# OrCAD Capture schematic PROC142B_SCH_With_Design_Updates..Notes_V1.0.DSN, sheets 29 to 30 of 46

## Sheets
29 28. BOOT MODE BUFFER & SWITCHES: size C; title: BOOT MODE CONFIGURATION BUFFERS & DIP SWITCHES
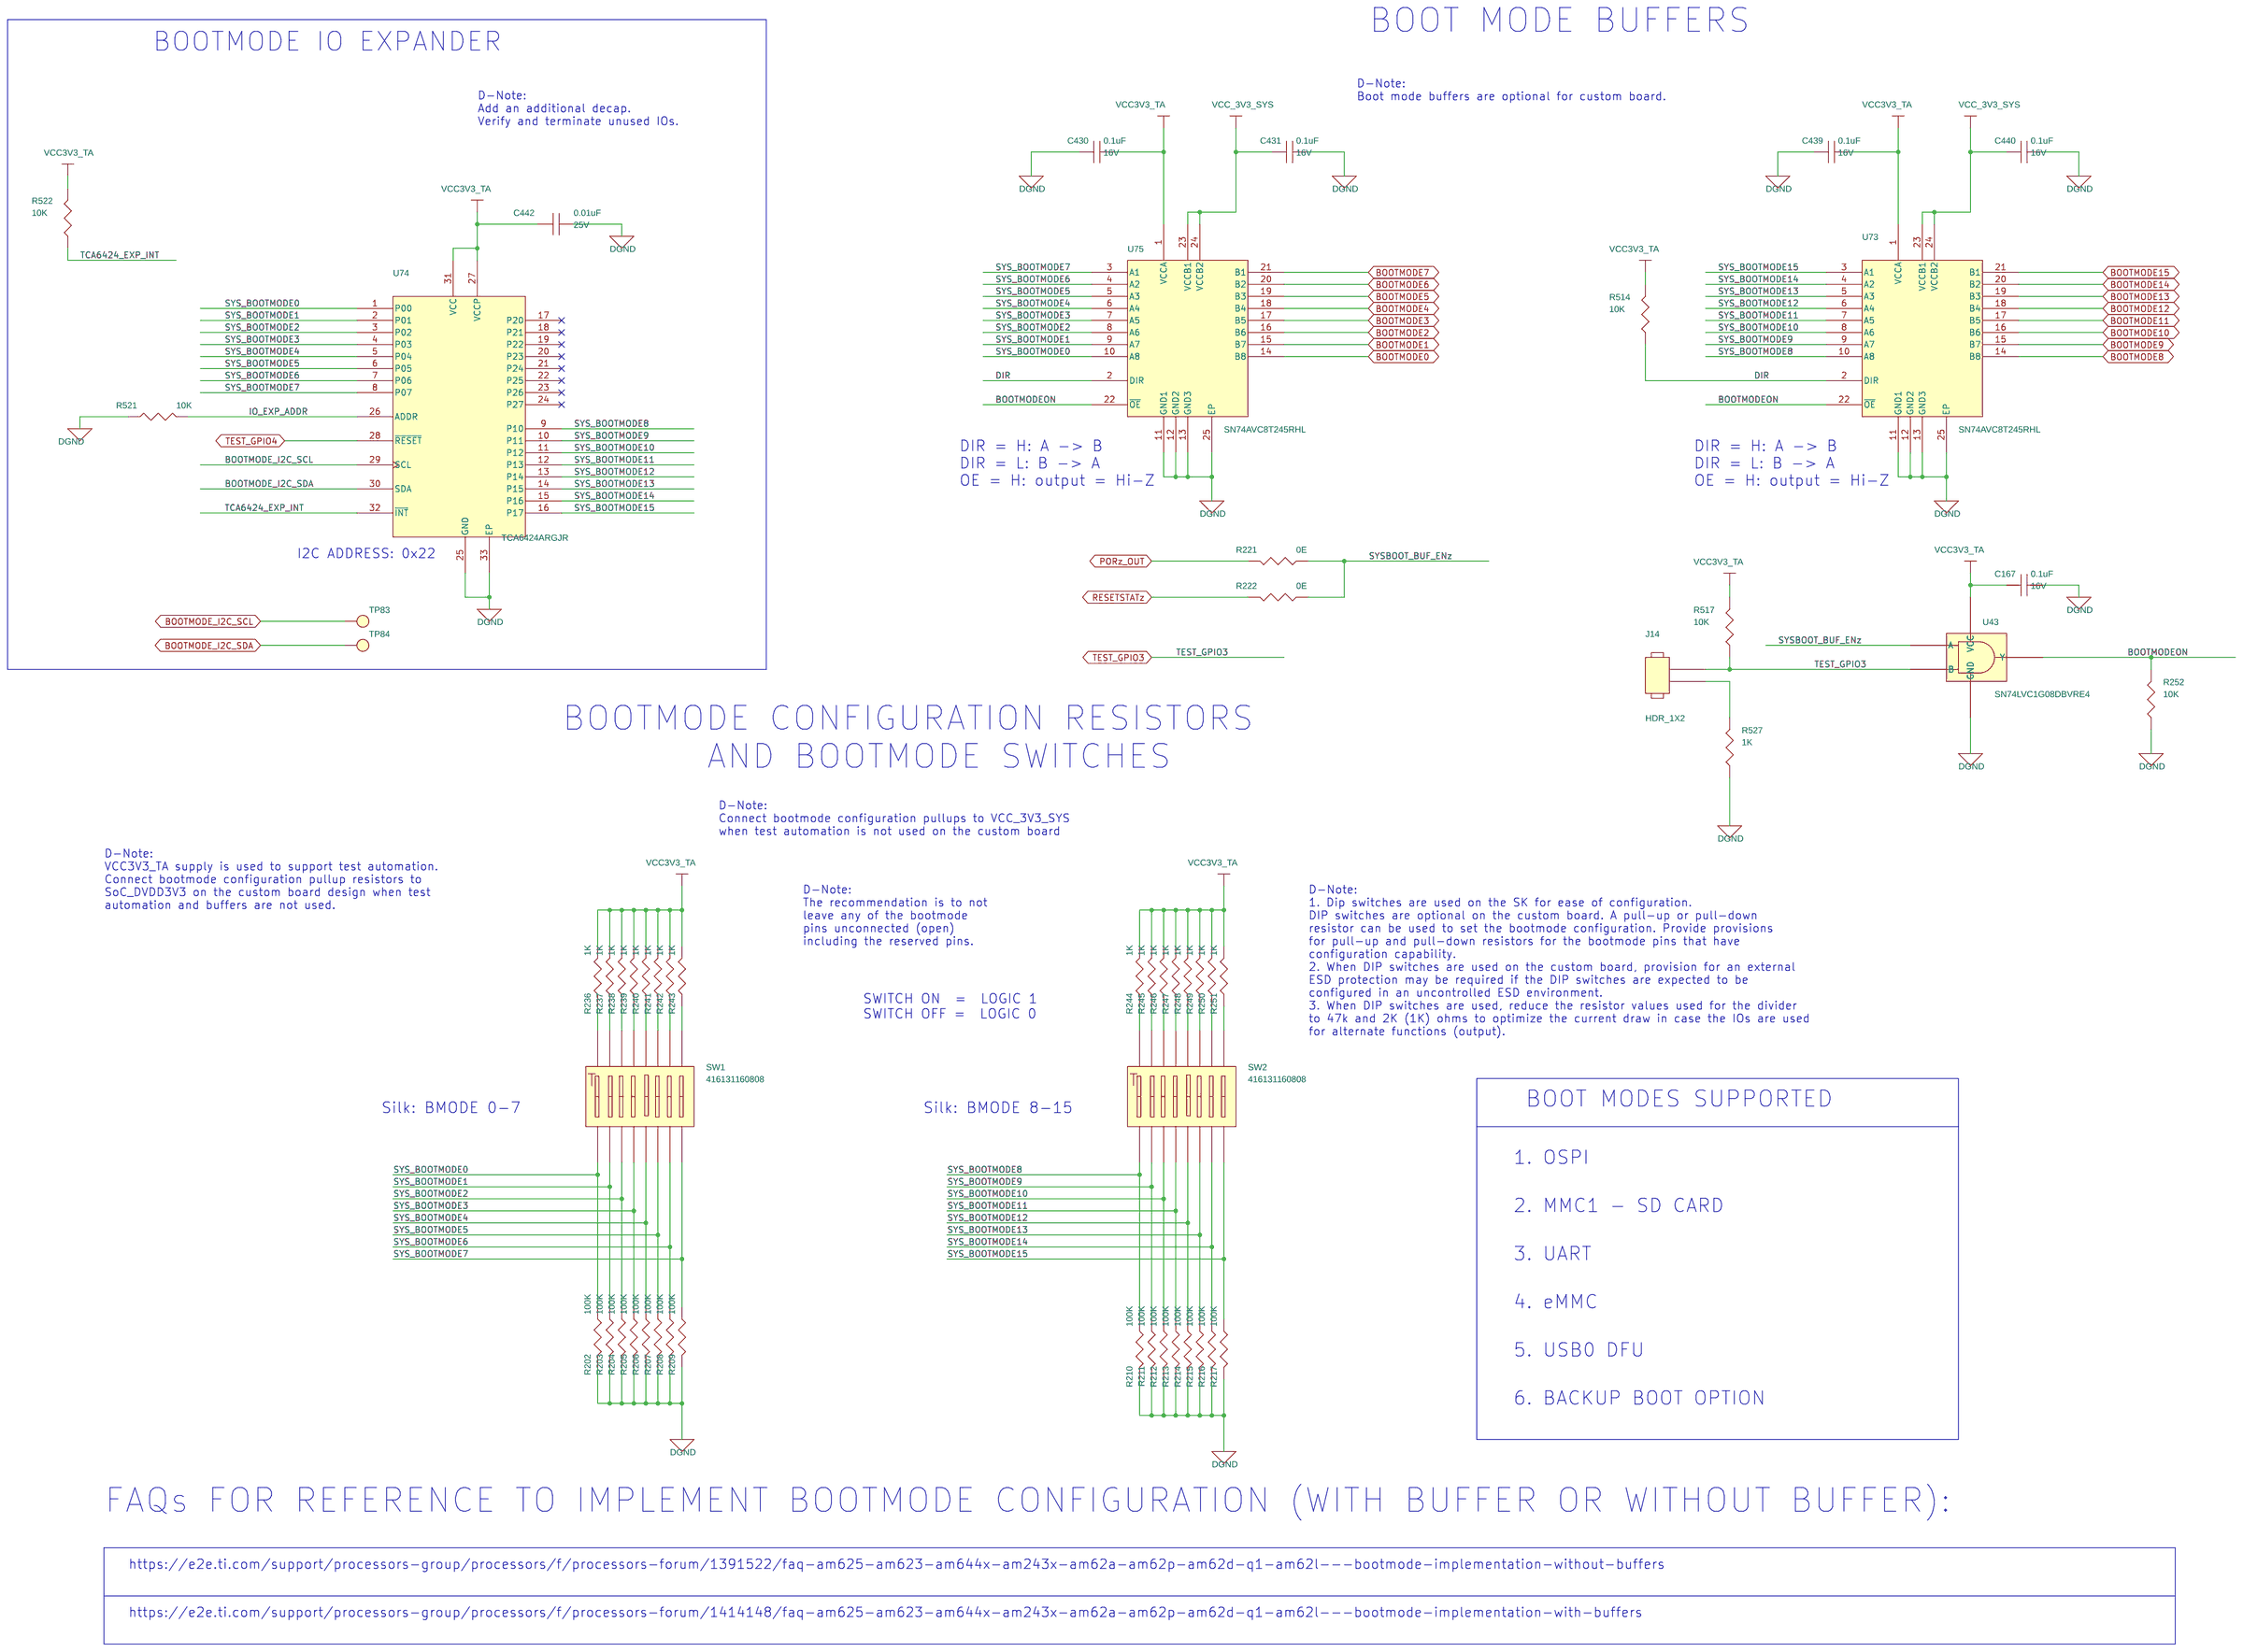
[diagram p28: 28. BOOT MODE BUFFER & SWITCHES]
30 29. XDS110 DEBUGGER: size C; title: XDS110 DEBUGGER
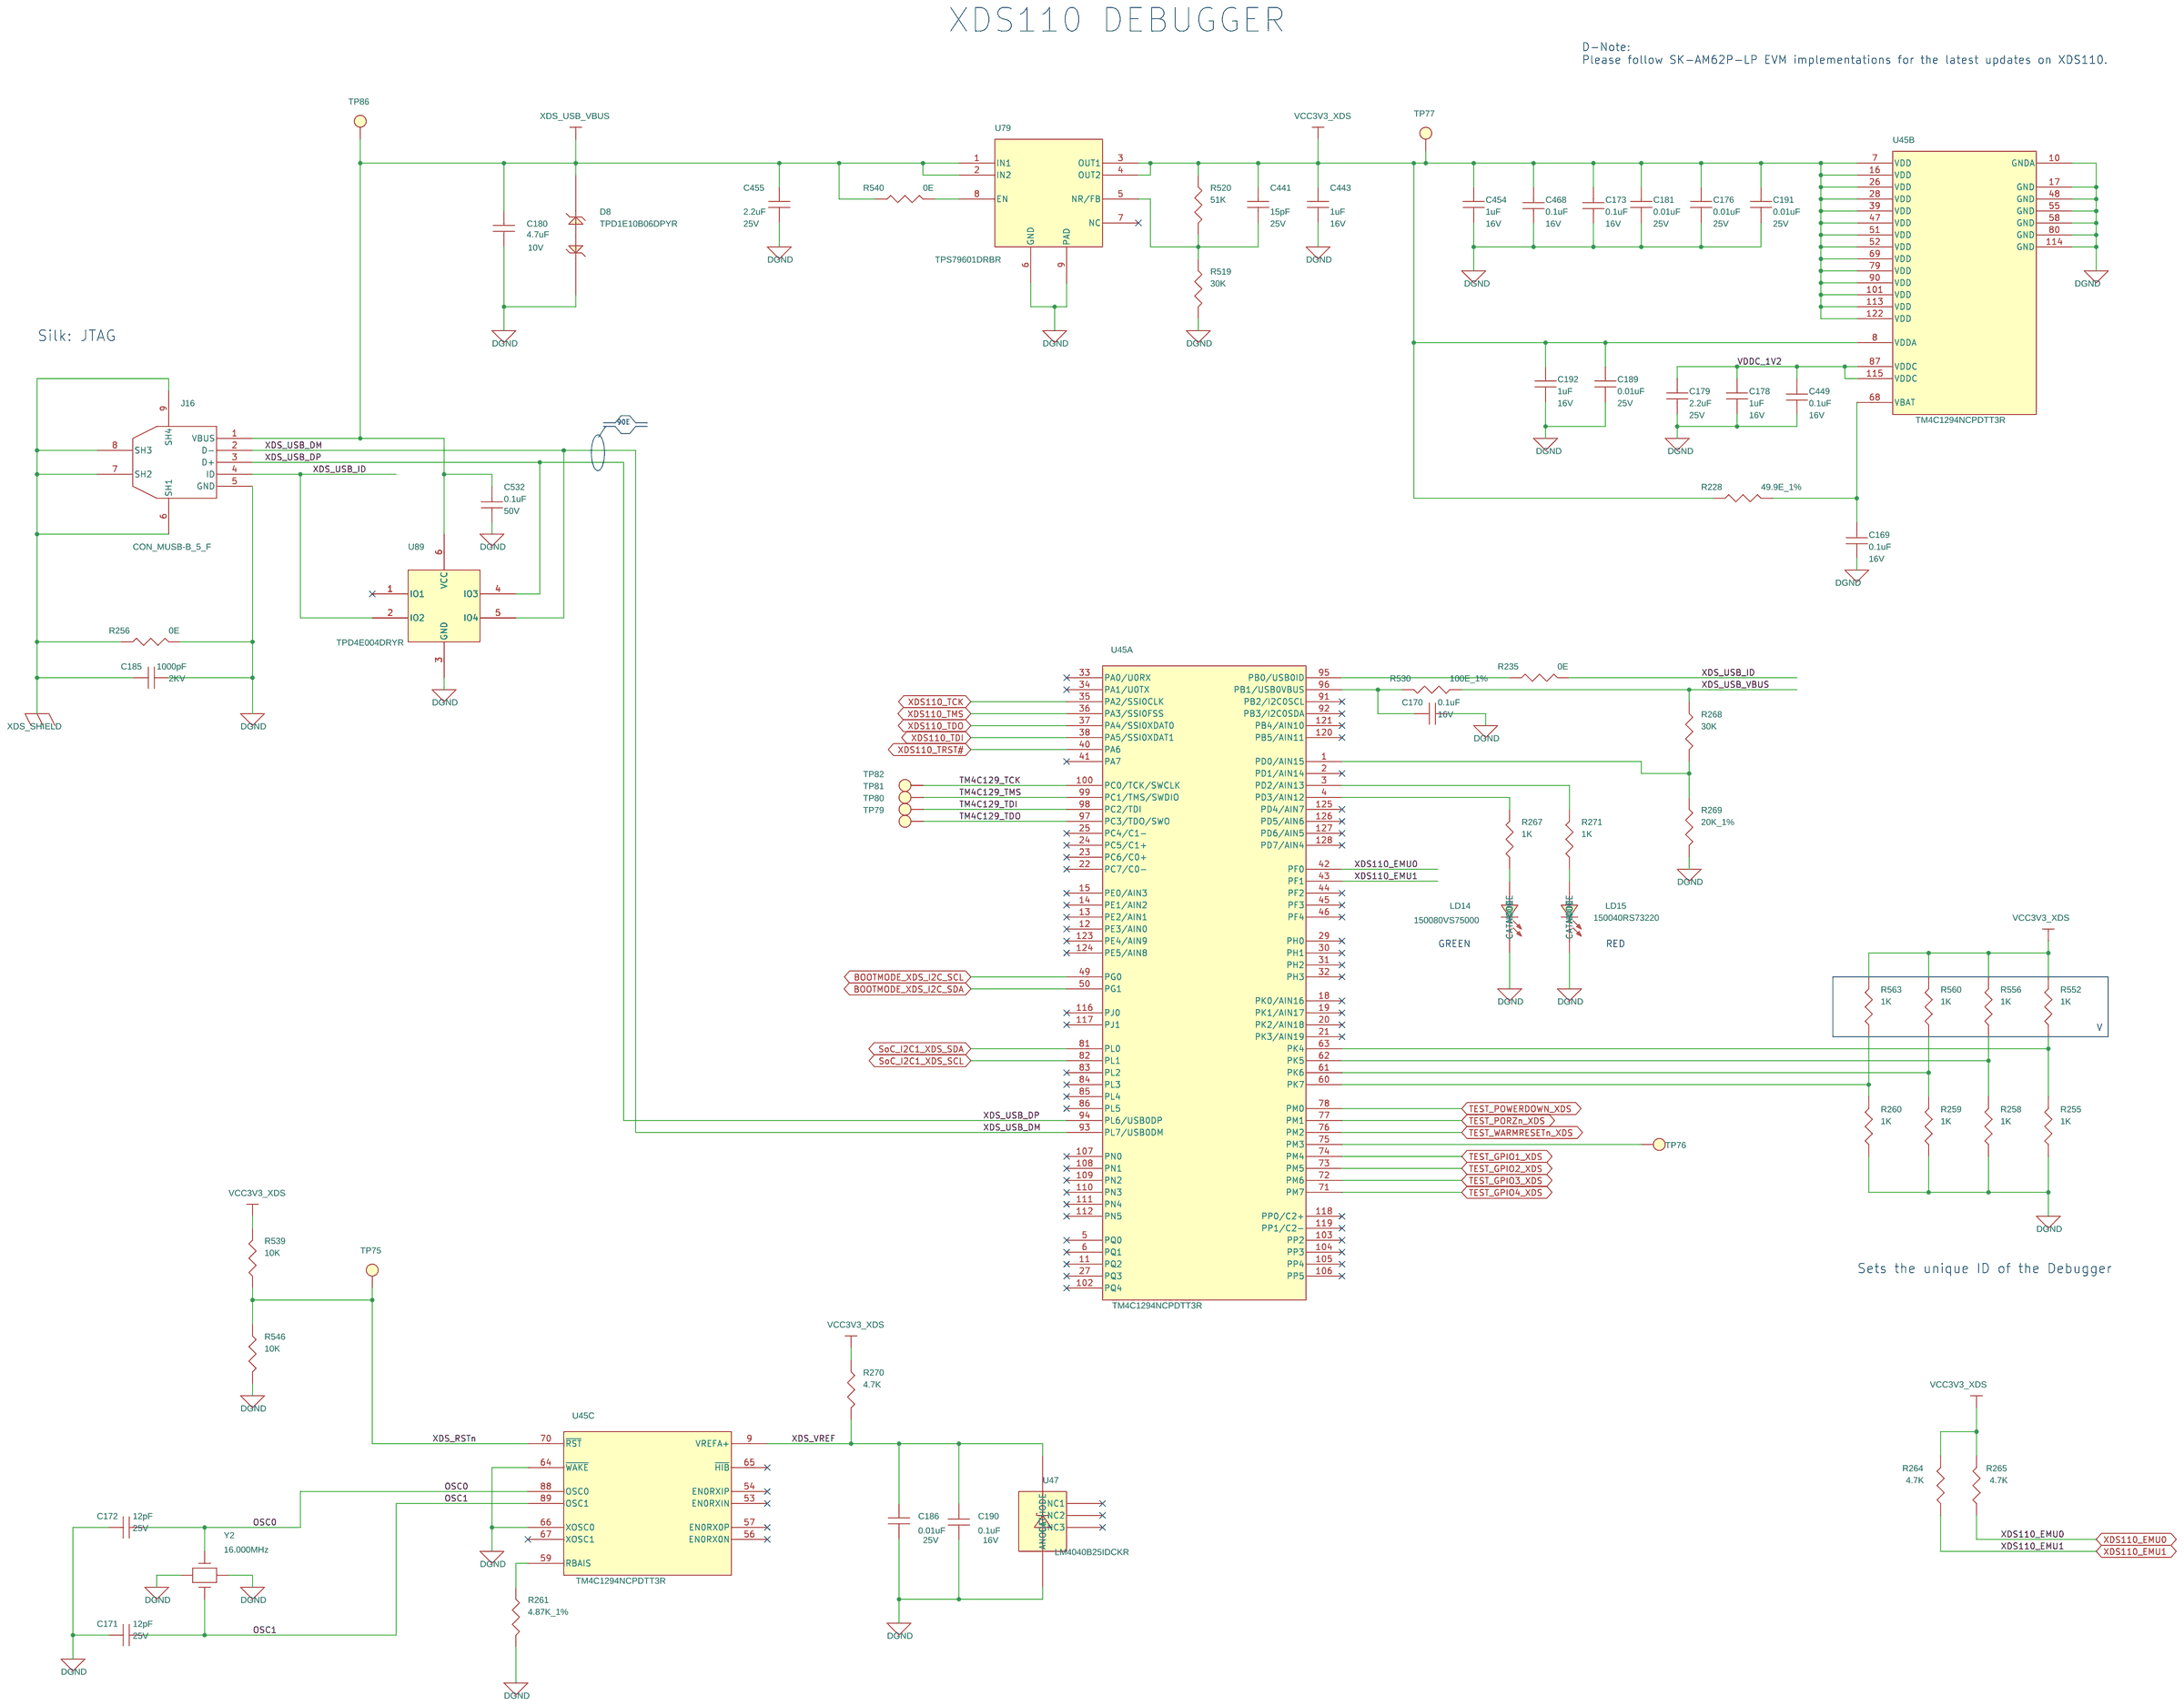
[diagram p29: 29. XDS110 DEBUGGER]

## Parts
sheet 28. BOOT MODE BUFFER & SWITCHES
C167  0.1uF  [CAP0201_0-5]
C430  0.1uF  [CAP0201_0-5]
C431  0.1uF  [CAP0201_0-5]
C439  0.1uF  [CAP0201_0-5]
C440  0.1uF  [CAP0201_0-5]
C442  0.01uF  [CAP0201_0-5]
J14  HDR_1X2  [HDR_1X2_90120-0122_S_T_5-6]
R202  100K  [RES0402_0-5]
R203  100K  [RES0402_0-5]
R204  100K  [RES0402_0-5]
R205  100K  [RES0402_0-5]
R206  100K  [RES0402_0-5]
R207  100K  [RES0402_0-5]
R208  100K  [RES0402_0-5]
R209  100K  [RES0402_0-5]
R210  100K  [RES0402_0-5]
R211  100K  [RES0402_0-5]
R212  100K  [RES0402_0-5]
R213  100K  [RES0402_0-5]
R214  100K  [RES0402_0-5]
R215  100K  [RES0402_0-5]
R216  100K  [RES0402_0-5]
R217  100K  [RES0402_0-5]
R221  0E  [RES0201_0-5]
R222  0E  [RES0402_0-5]
R236  1K  [RES0402_0-5]
R237  1K  [RES0402_0-5]
R238  1K  [RES0402_0-5]
R239  1K  [RES0402_0-5]
R240  1K  [RES0402_0-5]
R241  1K  [RES0402_0-5]
R242  1K  [RES0402_0-5]
R243  1K  [RES0402_0-5]
R244  1K  [RES0402_0-5]
R245  1K  [RES0402_0-5]
R246  1K  [RES0402_0-5]
R247  1K  [RES0402_0-5]
R248  1K  [RES0402_0-5]
R249  1K  [RES0402_0-5]
R250  1K  [RES0402_0-5]
R251  1K  [RES0402_0-5]
R252  10K  [RES0201_0-5]
R514  10K  [RES0201_0-5]
R517  10K  [RES0201_0-5]
R521  10K  [RES0201_0-5]
R522  10K  [RES0201_0-5]
R527  1K  [RES0402_0-5]
SW1  416131160808  [SW16_416131160808_460X230_SMD_2-7]
SW2  416131160808  [SW16_416131160808_460X230_SMD_2-7]
TP83  TP20_SMD  [TP20_SMD]
TP84  TP20_SMD  [TP20_SMD]
U43  SN74LVC1G08DBVRE4  [SOT23-5]
U73  SN74AVC8T245RHL  [QFN24_19-68_220X140_1]
U74  TCA6424ARGJR  [QFN32_19-68_200X200]
U75  SN74AVC8T245RHL  [QFN24_19-68_220X140_1]
sheet 29. XDS110 DEBUGGER
C169  0.1uF  [CAP0201_0-5]
C170  0.1uF  [CAP0201_0-5]
C171  12pF  [CAP0201_0-5]
C172  12pF  [CAP0201_0-5]
C173  0.1uF  [CAP0201_0-5]
C176  0.01uF  [CAP0201_0-5]
C178  1uF  [CAP0201_0-5]
C179  2.2uF  [CAP0402_0-75]
C180  4.7uF  [CAP0402_0-75]
C181  0.01uF  [CAP0201_0-5]
C185  1000pF  [CAP1206_1-75]
C186  0.01uF  [CAP0201_0-5]
C189  0.01uF  [CAP0201_0-5]
C190  0.1uF  [CAP0201_0-5]
C191  0.01uF  [CAP0201_0-5]
C192  1uF  [CAP0201_0-5]
C441  15pF  [CAP0201_0-5]
C443  1uF  [CAP0201_0-5]
C449  0.1uF  [CAP0201_0-5]
C454  1uF  [CAP0201_0-5]
C455  2.2uF  [CAP0402_0-75]
C468  0.1uF  [CAP0201_0-5]
C532  0.1uF  [CAP0402_0-75]
D8  TPD1E10B06DPYR  [DIO_DFN0402_0-5]
J16  CON_MUSB-B_5_F  [CON_MUSBB5_629105150521_S_R_S_2-7]
LD14  150080VS75000  [LED_150080VS75000_80X50_SMD_0-8]
LD15  150040RS73220  [LED_150040GS73220_40X20_SMD_0-4]
R228  49.9E_1%  [RES0402_0-5]
R235  0E  [RES0402_0-5]
R255  1K  [RES0402_0-5]
R256  0E  [RES0603_0-75]
R258  1K  [RES0402_0-5]
R259  1K  [RES0402_0-5]
R260  1K  [RES0402_0-5]
R261  4.87K_1%  [RES0402]
R264  4.7K  [RES0201_0-5]
R265  4.7K  [RES0201_0-5]
R267  1K  [RES0402_0-5]
R268  30K  [RES0402_0-5]
R269  20K_1%  [RES0402_0-5]
R270  4.7K  [RES0201_0-5]
R271  1K  [RES0402_0-5]
R519  30K  [RES0402_0-5]
R520  51K  [RES0402_0-5]
R530  100E_1%  [RES0402_0-5]
R539  10K  [RES0201_0-5]
R540  0E  [RES0201_0-5]
R546  10K  [RES0201_0-5]
R552  1K  [RES0402_0-5]
R556  1K  [RES0402_0-5]
R560  1K  [RES0402_0-5]
R563  1K  [RES0402_0-5]
TP75  TP20_SMD  [TP20_SMD]
TP76  TP20_SMD  [TP20_SMD]
TP77  TP20_SMD  [TP20_SMD]
TP79  TP20_SMD  [TP20_SMD]
TP80  TP20_SMD  [TP20_SMD]
TP81  TP20_SMD  [TP20_SMD]
TP82  TP20_SMD  [TP20_SMD]
TP86  TP20_SMD  [TP20_SMD]
U45  TM4C1294NCPDTT3R  [TQFP128_15-74_550X550_1-2]  (sections A,B,C)
U47  LM4040B25IDCKR  [SC70-5_1-1]
U79  TPS79601DRBR  [SON8_25-59_130X130_1]
U89  TPD4E004DRYR  [SON6_19-68_40X60_PB_0-6]
Y2  16.000MHz  [XTAL4_XRCGB-FM_80X60_SMD_0-7]

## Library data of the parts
C167 C169 C170 C173 C190 C430 C431 C439 C440 C449 C468 = CAP: CAP CERAMIC 0.1uF 16V 10% X5R 0201; Alt_Mfr_name: YAGEO AMERICA; Alt_Mfr_part_number: CC0402KRX5R8BB104; Chkd/date: MANIRAJA/230118; Crtd /date: MANIRAJA/230118; Custom_Duty: 15%; Customs_HS_Code: 85322990; Distributor_name: DIGIKEY; Distributor_part_number: 490-14305-1-ND; Footprint Path: Y:\MIS_DATABASE\Library\ALTIUM_TOOL\PCB_FOOTPRINTS\Altium_Footprint_Lib.PcbLib; Height: 0.33MM; Library Path: Y:\MIS_DATABASE\Library\ALTIUM_TOOL\SCHEMATICS_PARTS\MS_DISCRETE_Library.schlib; Mfr_name: MURATA; Mfr_part_number: GRM033R61C104KE14D; Mistral Part No: 120009030072-R; Package: 0201; Part_type: CAPACITORS\CERAMIC; Project: TI_MAXIE_CPB; RoHS: RoHS; Temperature: -55°C+85°C; Tolerance: 10%; Voltage: 16V; Wattage: NA; Weight: 0.33mg; Datasheet: Y:\MIS_DATABASE\DATASHEETS\CAPACITORS\GRM033R61C104KE14.PDF
C176 C181 C186 C189 C191 C442 = CAP: CAP CERAMIC 0.01uF 25V 10% X5R 0201; Chkd/date: MANIRAJA/230118; Crtd /date: MANIRAJA/230118; Custom_Duty: 15%; Customs_HS_Code: 85322990; Distributor_name: DIGIKEY; Distributor_part_number: GRM033R61E103KA12J-ND; Footprint Path: Y:\MIS_DATABASE\Library\ALTIUM_TOOL\PCB_FOOTPRINTS\Altium_Footprint_Lib.PcbLib; Height: 0.33MM; Library Path: Y:\MIS_DATABASE\Library\ALTIUM_TOOL\SCHEMATICS_PARTS\MS_DISCRETE_Library.schlib; Mfr_name: MURATA; Mfr_part_number: GRM033R61E103KA12J; Mistral Part No: 120018010007-R; Package: 0201; Part_type: CAPACITORS\CERAMIC; Project: TI_MAXIE_CPB; RoHS: RoHS; Temperature: -55°C+85°C; Tolerance: 10%; Voltage: 25V; Wattage: NA; Weight: 0.33mg; Datasheet: Y:\MIS_DATABASE\DATASHEETS\CAPACITORS\GRM033R61E103KA12.PDF
J14 = HEADER_2X1: CON HDR 1X2 2.54MM PITCH ST TH; Chkd/date: NAVEED/210714; Crtd /date: USMAN/031012; Custom_Duty: 24%; Customs_HS_Code: 85369090; Distributor_name: DIGIKEY; Distributor_part_number: WM8072-ND; Footprint Path: Y:\MIS_DATABASE\Library\ALTIUM_TOOL\PCB_FOOTPRINTS\Altium_Footprint_Lib.PcbLib; Height: 5.60MM; Library Path: Y:\MIS_DATABASE\Library\ALTIUM_TOOL\SCHEMATICS_PARTS\MS_CONNECTOR_Library.schlib; Mfr_name: MOLEX; Mfr_part_number: 90120-0122; Mistral Part No: 150012100005-R; Package: THRU-HOLE; Part_type: CONNECTOR\HEADERS; Project: NPOL_FEP; RoHS: RoHS; Temperature: -55°C+125°C; Tolerance: NA; Voltage: NA; Wattage: NA; Weight: 122mg; Datasheet: Y:\MIS_DATABASE\DATASHEETS\CONNECTORS\90120-XX.PDF
R202-R217 = RESISTOR: RES 100K 1/16W 5% 0402; Chkd/date: MANIRAJA/100717; Crtd /date: MANIRAJA/100717; Custom_Duty: 15%; Customs_HS_Code: 85332119; Distributor_name: DIGIKEY; Distributor_part_number: 311-100KJRCT-ND; Footprint Path: Y:\MIS_DATABASE\Library\ALTIUM_TOOL\PCB_FOOTPRINTS\Altium_Footprint_Lib.PcbLib; Height: 0.40MM; Library Path: Y:\MIS_DATABASE\Library\ALTIUM_TOOL\SCHEMATICS_PARTS\MS_DISCRETE_Library.schlib; Mfr_name: YAGEO AMERICA; Mfr_part_number: RC0402JR-07100KL; Mistral Part No: 110011060002-R; Package: 0402; Part_type: RESISTORS\FIXED; Project: DM8147_PCI CARD; RoHS: RoHS; Temperature: -55°C+155°C; Tolerance: 5%; Voltage: NA; Wattage: 1/16W; Weight: 0.65mg; Datasheet: Y:\MIS_DATABASE\DATASHEETS\RESISTORS\RCXXXXL-SER_MAR18.PDF
R221 R540 = RESISTOR: RES 0E 1/20W 5% 0201; Chkd/date: NAVEED/301214; Crtd /date: MUDDU/120710; Custom_Duty: 15%; Customs_HS_Code: 85332119; Distributor_name: DIGIKEY; Distributor_part_number: 311-0.0NCT-ND; Footprint Path: Y:\MIS_DATABASE\Library\ALTIUM_TOOL\PCB_FOOTPRINTS\Altium_Footprint_Lib.PcbLib; Height: 0.26MM; Library Path: Y:\MIS_DATABASE\Library\ALTIUM_TOOL\SCHEMATICS_PARTS\MS_DISCRETE_Library.schlib; Mfr_name: YAGEO AMERICA; Mfr_part_number: RC0201JR-070RL; Mistral Part No: 110010070067-R; Package: 0201; Part_type: RESISTORS\FIXED; Project: PB_BUGBASE; RoHS: RoHS; Temperature: -55°C+125°C; Tolerance: 5%; Voltage: NA; Wattage: 1/20W; Weight: 0.17mg; Datasheet: Y:\MIS_DATABASE\DATASHEETS\RESISTORS\RCXXXXL-SER_MAR18.PDF
R222 R235 = RESISTOR: RES 0E 1/16W JUMPER 0402; Chkd/date: VASANTHA/201216; Crtd /date: MUDDU/190810; Custom_Duty: 15%; Customs_HS_Code: 85332119; Distributor_name: DIGIKEY; Distributor_part_number: 541-0.0JCT-ND; Footprint Path: Y:\MIS_DATABASE\Library\ALTIUM_TOOL\PCB_FOOTPRINTS\Altium_Footprint_Lib.PcbLib; Height: 0.40MM; Library Path: Y:\MIS_DATABASE\Library\ALTIUM_TOOL\SCHEMATICS_PARTS\MS_DISCRETE_Library.schlib; Mfr_name: VISHAY; Mfr_part_number: CRCW04020000Z0ED; Mistral Part No: 110010080019-R; Package: 0402; Part_type: RESISTORS\FIXED; Project: PB_BUGBASE; RoHS: RoHS; Temperature: -55°C+155°C; Tolerance: NA; Voltage: NA; Wattage: 1/16W; Weight: 0.65mg; Datasheet: Y:\MIS_DATABASE\DATASHEETS\RESISTORS\CRCW0603.PDF
R236-R251 R255 R258-R260 R267 R271 R527 R552 R556 R560 R563 = RESISTOR: RES 1K 1/10W 5% 0402; Chkd/date: VASANTHA/201216; Crtd /date: MAZHAR/230805; Custom_Duty: 15%; Customs_HS_Code: 85332119; Distributor_name: DIGIKEY; Distributor_part_number: P1.0KJCT-ND; Footprint Path: Y:\MIS_DATABASE\Library\ALTIUM_TOOL\PCB_FOOTPRINTS\Altium_Footprint_Lib.PcbLib; Height: 0.40MM; Library Path: Y:\MIS_DATABASE\Library\ALTIUM_TOOL\SCHEMATICS_PARTS\MS_DISCRETE_Library.schlib; Mfr_name: PANASONIC-ECG; Mfr_part_number: ERJ-2GEJ102X; Mistral Part No: 110009030400-R; Package: 0402; Part_type: RESISTORS\FIXED; Project: HSE; RoHS: RoHS; Temperature: -55°C+155°C; Tolerance: 5%; Voltage: NA; Wattage: 1/10W; Weight: 0.8mg; Datasheet: Y:\MIS_DATABASE\DATASHEETS\RESISTORS\PAN-ERJSER_NOV17.PDF
R252 R514 R517 R521 R522 R539 R546 = RESISTOR: RES 10K 1/20W 5% 0201; Chkd/date: MANIRAJA/050517; Crtd /date: MANIRAJA/050517; Custom_Duty: 15%; Customs_HS_Code: 85332119; Distributor_name: DIGIKEY; Distributor_part_number: 311-10KNCT-ND; Footprint Path: Y:\MIS_DATABASE\Library\ALTIUM_TOOL\PCB_FOOTPRINTS\Altium_Footprint_Lib.PcbLib; Height: 0.26MM; Library Path: Y:\MIS_DATABASE\Library\ALTIUM_TOOL\SCHEMATICS_PARTS\MS_DISCRETE_Library.schlib; Mfr_name: YAGEO AMERICA; Mfr_part_number: RC0201JR-0710KL; Mistral Part No: 110010070051-R; Package: 0201; Part_type: RESISTORS\FIXED; Project: GOLDEN-I LITE; RoHS: RoHS; Temperature: -55°C+125°C; Tolerance: 5%; Voltage: NA; Wattage: 1/20W; Weight: 0.17mg; Datasheet: Y:\MIS_DATABASE\DATASHEETS\RESISTORS\RCXXXXL-SER_MAR18.PDF
SW1 SW2 = SW16_CHS-08A: SWITCH SLIDE SPST ST SMD; Chkd/date: MANIRAJA/051020; Crtd /date: ALVY/011020; Custom_Duty: 24%; Customs_HS_Code: 85369090; Distributor_name: DIGIKEY; Distributor_part_number: 732-3857-1-ND; Footprint Path: Y:\MIS_DATABASE\Library\ALTIUM_TOOL\PCB_FOOTPRINTS\Altium_Footprint_Lib.PcbLib; Height: 2.65MM; Library Path: Y:\MIS_DATABASE\Library\ALTIUM_TOOL\SCHEMATICS_PARTS\MS_SWITCH_Library.schlib; Mfr_name: WURTH ELECTRONICS; Mistral Part No: 130020100001-R; Package: SMD; Part_type: ELECTRO-MECHANICAL\SWITCH; Project: AM64X_SKEVM; RoHS: RoHS; Temperature: -40°C+85°C; Tolerance: NA; Voltage: NA; Wattage: NA; Weight: 281.7mg; Datasheet: Y:\MIS_DATABASE\DATASHEETS\MISC\SWITCHES\4161311608XX.PDF
TP75-TP77 TP79-TP84 TP86 = TESTPOINT: TESTPOINT CIR 20 SMD; Chkd/date: SHREESHAIL/171006; Crtd /date: MAZHAR/171006; Custom_Duty: NA; Customs_HS_Code: NA; Distributor_name: NA; Distributor_part_number: NA; Footprint Path: Y:\MIS_DATABASE\Library\ALTIUM_TOOL\PCB_FOOTPRINTS\Altium_Footprint_Lib.PcbLib; Height: NA; Library Path: Y:\MIS_DATABASE\Library\ALTIUM_TOOL\SCHEMATICS_PARTS\MS_DISCRETE_Library.schlib; MECHANICAL 3D STEP FILE: NA; Mfr_name: LOCAL; Mistral Part No: NA; Package: SMD; Project: BT MODULE_CSRBC04; RoHS: NA; Temperature: NA; Tolerance: NA; Voltage: NA; Wattage: NA; Weight: NA; Datasheet: NA
U43 = SN74LVC1G08DBVRE4_SOT23-5: IC SINGLE 2-INPUT POSITIVE AND GATE SOT23-5; Chkd/date: SUHAS/221010; Crtd /date: USMAN/151008; Custom_Duty: 15%; Customs_HS_Code: 85423100; Distributor_name: DIGIKEY; Distributor_part_number: SN74LVC1G08DBVRE4-ND; Height: 1.45MM; Mfr_name: TEXAS INSTRUMENTS; Mistral Part No: 141009060026-R; Part_type: ICS\DIGITAL\GATES; Project: KHAN_MAIN; RoHS: Sb/ Br FREE; Temperature: -40°C+85°C; Datasheet: Y:\MIS_DATABASE\DATASHEETS\ICS\DIGITAL\GATES\SN74LVC1G08.PDF
U73 U75 = SN74AVC8T245RHL_QFN24: IC BUS TRANSCEIVER 8-BIT DUAL-SUPPLY QFN24; Chkd/date: VASANTHA/231216; Crtd /date: BAVISH/290411; Custom_Duty: 15%; Customs_HS_Code: 85423100; Distributor_name: DIGIKEY; Distributor_part_number: 296-17859-1-ND; Height: 1.00MM; Mfr_name: TEXAS INSTRUMENTS; Mfr_part_number: SN74AVC8T245RHLR; Mistral Part No: 143011040001-R; Package: QFN24; Part_type: ICS\TELECOM\TRANSCEIVER; Project: OMAPL1_PEC20; RoHS: RoHS; Temperature: -40°C+85°C; Tolerance: NA; Voltage: NA; Wattage: NA; Weight: NA; Datasheet: Y:\MIS_DATABASE\DATASHEETS\ICS\DIGITAL\BUSTRANSCEIVER\SN74AVC8T245.PDF
U74 = TCA6424ARGJR_QFN32: IC I2C I/O EXPANDER 24B UQFN32; Chkd/date: NAVEED/100715; Crtd /date: NAVEED/100914; Custom_Duty: 15%; Customs_HS_Code: 85423100; Distributor_name: DIGIKEY; Distributor_part_number: 296-27844-1-ND; Height: 0.60MM; Mfr_name: TEXAS INSTRUMENTS; Mistral Part No: 141014090009-R; Package: UQFN32; Part_type: ICS\DIGITAL\BUSTRANSCEIVER; Project: ZK_BIOMETRIC; RoHS: RoHS; Temperature: -40°C+85°C; Weight: NA; Datasheet: Y:\MIS_DATABASE\DATASHEETS\ICS\DIGITAL\BUSTRANSCEIVER\TCA6424AR.PDF
C171 C172 = CAP: CAP CERAMIC 12pF 25V 5% C0G(NP0) 0201; Chkd/date: MANIRAJA/020620; Crtd /date: ALVY/300520; Custom_Duty: 15%; Customs_HS_Code: 85322990; Distributor_name: DIGIKEY; Distributor_part_number: 490-3144-1-ND; Footprint Path: Y:\MIS_DATABASE\Library\ALTIUM_TOOL\PCB_FOOTPRINTS\Altium_Footprint_Lib.PcbLib; Height: 0.33MM; Library Path: Y:\MIS_DATABASE\Library\ALTIUM_TOOL\SCHEMATICS_PARTS\MS_DISCRETE_Library.schlib; Mfr_name: MURATA; Mfr_part_number: GRM0335C1E120JA01D; Mistral Part No: 120009030213-R; Package: 0201; Part_type: CAPACITORS\CERAMIC; Project: QCS610_NANOSOM; RoHS: RoHS; Temperature: -55°C+125°C; Tolerance: 5%; Voltage: 25V; Wattage: NA; Weight: 0.33mg; Datasheet: Y:\MIS_DATABASE\DATASHEETS\CAPACITORS\GRM0335C1E120JA01.PDF
C178 C192 C443 C454 = CAP: CAP CERAMIC 1uF 16V 20% X5R 0201; Chkd/date: MANIRAJA/300520; Crtd /date: ALVY/260520; Custom_Duty: 15%; Customs_HS_Code: 85322990; Distributor_name: DIGIKEY; Distributor_part_number: 490-18654-1-ND; Footprint Path: Y:\MIS_DATABASE\Library\ALTIUM_TOOL\PCB_FOOTPRINTS\Altium_Footprint_Lib.PcbLib; Height: 0.39MM; Library Path: Y:\MIS_DATABASE\Library\ALTIUM_TOOL\SCHEMATICS_PARTS\MS_DISCRETE_Library.schlib; Mfr_name: MURATA; Mfr_part_number: GRM033R61C105ME15D; Mistral Part No: 120018090038-R; Package: 0201; Part_type: CAPACITORS\CERAMIC; Project: QCS610_NANOSOM; RoHS: RoHS; Temperature: -55°C+85°C; Tolerance: 20%; Voltage: 16V; Wattage: NA; Weight: 0.33mg; Datasheet: Y:\MIS_DATABASE\DATASHEETS\CAPACITORS\GRM033R61C105ME15.PDF
C179 C455 = CAP: CAP CERAMIC 2.2uF 25V 10% X5R 0402; Chkd/date: ALVY/010721; Crtd /date: MANIRAJA/010721; Custom_Duty: 15%; Customs_HS_Code: 85322990; Distributor_name: DIGIKEY; Distributor_part_number: 490-12703-1-ND; Footprint Path: Y:\MIS_DATABASE\Library\ALTIUM_TOOL\PCB_FOOTPRINTS\Altium_Footprint_Lib.PcbLib; Height: 0.70MM; Library Path: Y:\MIS_DATABASE\Library\ALTIUM_TOOL\SCHEMATICS_PARTS\MS_DISCRETE_Library.schlib; Mfr_name: MURATA; Mfr_part_number: GRM155R61E225KE11D; Mistral Part No: 120015120001-R; Package: 0402; Part_type: CAPACITORS\CERAMIC; Project: TI_AM263X_CC; RoHS: RoHS; Temperature: -55°C+85°C; Tolerance: 10%; Voltage: 25V; Wattage: NA; Weight: 1.5mg; Datasheet: Y:\MIS_DATABASE\DATASHEETS\CAPACITORS\GRM155R61E225KE11.PDF
C180 = CAP: CAP CERAMIC 4.7uF 10V 20% X5R 0402; Chkd/date: MANIRAJA/110718; Crtd /date: ALVY/110718; Custom_Duty: 15%; Customs_HS_Code: 85322990; Distributor_name: DIGIKEY; Distributor_part_number: 490-14306-1-ND; Footprint Path: Y:\MIS_DATABASE\Library\ALTIUM_TOOL\PCB_FOOTPRINTS\Altium_Footprint_Lib.PcbLib; Height: 0.65MM; Library Path: Y:\MIS_DATABASE\Library\ALTIUM_TOOL\SCHEMATICS_PARTS\MS_DISCRETE_Library.schlib; Mfr_name: MURATA; Mfr_part_number: GRM155R61A475MEAAD; Mistral Part No: 120012060002-R; Package: 0402; Part_type: CAPACITORS\CERAMIC; Project: TI_J7SVB_PCIE_ADD-ON-CARD; RoHS: RoHS; Temperature: -55°C+85°C; Tolerance: 20%; Voltage: 10V; Wattage: NA; Weight: 14mg; Datasheet: Y:\MIS_DATABASE\DATASHEETS\CAPACITORS\GRM155R61A475MEAAD.PDF
C185 = CAP: CAP CERAMIC 1000pF 2KV 10% X7R 1206; Chkd/date: SHREESHAIL/291106; Crtd /date: MAZHAR/281106; Custom_Duty: 15%; Customs_HS_Code: 85322990; Distributor_name: DIGIKEY; Distributor_part_number: 478-2956-1-ND; Footprint Path: Y:\MIS_DATABASE\Library\ALTIUM_TOOL\PCB_FOOTPRINTS\Altium_Footprint_Lib.PcbLib; Height: 1.52MM; Library Path: Y:\MIS_DATABASE\Library\ALTIUM_TOOL\SCHEMATICS_PARTS\MS_DISCRETE_Library.schlib; Mfr_name: AVX CORPORATION; Mfr_part_number: 1206GC102KAT1A; Mistral Part No: 120015080006-R; Package: 1206; Part_type: CAPACITORS\CERAMIC; Project: ADR1B; RoHS: RoHS; Temperature: -55°C+125°C; Tolerance: 10%; Voltage: 2KV; Wattage: NA; Weight: 16.2mg; Datasheet: Y:\MIS_DATABASE\DATASHEETS\CAPACITORS\AVX_HV-MLC.PDF
C441 = CAP: CAP CERAMIC 15pF 25V 2% HI-Q C0G(NP0) 0201; Chkd/date: VASANTHA/081216; Crtd /date: MANIRAJA/081216; Custom_Duty: 15%; Customs_HS_Code: 85322990; Distributor_name: DIGIKEY; Distributor_part_number: 490-10562-1-ND; Footprint Path: Y:\MIS_DATABASE\Library\ALTIUM_TOOL\PCB_FOOTPRINTS\Altium_Footprint_Lib.PcbLib; Height: 0.33MM; Library Path: Y:\MIS_DATABASE\Library\ALTIUM_TOOL\SCHEMATICS_PARTS\MS_DISCRETE_Library.schlib; Mfr_name: MURATA; Mfr_part_number: GJM0335C1E150GB01D; Mistral Part No: 120016120011-R; Package: 0201; Part_type: CAPACITORS\CERAMIC; Project: OCTBTS5200; RoHS: RoHS; Temperature: -55°C+125°C; Tolerance: 2%; Voltage: 25V; Wattage: NA; Weight: 0.33mg; Datasheet: Y:\MIS_DATABASE\DATASHEETS\CAPACITORS\MURATA-GXX-SER_NOV17.PDF
C532 = CAP: CAP CERAMIC 0.1uF 50V 10% X7R 0402; Alt_Mfr_name: YAGEO AMERICA; Alt_Mfr_part_number: CC0402KRX5R8BB104; Chkd/date: MANIRAJA/261020; Crtd /date: ALVY/211020; Custom_Duty: 15%; Customs_HS_Code: 85322990; Distributor_name: DIGIKEY; Distributor_part_number: 490-10700-1-ND; Footprint Path: Y:\MIS_DATABASE\Library\ALTIUM_TOOL\PCB_FOOTPRINTS\Altium_Footprint_Lib.PcbLib; Height: 0.55MM; Library Path: Y:\MIS_DATABASE\Library\ALTIUM_TOOL\SCHEMATICS_PARTS\MS_DISCRETE_Library.schlib; Mfr_name: MURATA; Mfr_part_number: GRM155R71H104KE14D; Mistral Part No: 120011100014-R; Package: 0402; Part_type: CAPACITORS\CERAMIC; Project: J7_CP; RoHS: RoHS; Temperature: -55°C+125°C; Tolerance: 10%; Voltage: 50V; Wattage: NA; Weight: 3.1mg; Datasheet: Y:\MIS_DATABASE\DATASHEETS\CAPACITORS\GRM155R71H104KE14.PDF
D8 = DIODE_SOD323: DIODE 1CH ESD PROTECTION X1SON2; Chkd/date: MANIRAJA/040420; Crtd /date: VASANTHA/181114; Custom_Duty: 15%; Customs_HS_Code: 85423100; Distributor_name: DIGIKEY; Distributor_part_number: 296-30406-1-ND; Footprint Path: Y:\MIS_DATABASE\Library\ALTIUM_TOOL\PCB_FOOTPRINTS\Altium_Footprint_Lib.PcbLib; Height: 0.45MM; Library Path: Y:\MIS_DATABASE\Library\ALTIUM_TOOL\SCHEMATICS_PARTS\MS_DISCRETE_Library.schlib; Mfr_name: TEXAS INSTRUMENTS; Mistral Part No: 130014110022-R; Package: X1SON2; Part_type: DIODE; Project: GALILEO_EVM; RoHS: RoHS; Temperature: -40°C+125°C; Tolerance: NA; Voltage: NA; Wattage: NA; Weight: 1mg; Datasheet: Y:\MIS_DATABASE\DATASHEETS\ICS\INTERFACE\TPD1E10B06-SER.PDF
J16 = CON_USB_MINI-B: CON MICRO USB TYPE B 5POS FEMALE RT SMD; Chkd/date: MANIRAJA/150519; Crtd /date: ALVY/150519; Custom_Duty: 24%; Customs_HS_Code: 85369090; Distributor_name: DIGIKEY; Distributor_part_number: 732-5960-1-ND; Footprint Path: Y:\MIS_DATABASE\Library\ALTIUM_TOOL\PCB_FOOTPRINTS\Altium_Footprint_Lib.PcbLib; Height: 2.66MM; Library Path: Y:\MIS_DATABASE\Library\ALTIUM_TOOL\SCHEMATICS_PARTS\MS_CONNECTOR_Library.schlib; Mfr_name: WURTH ELECTRONICS; Mfr_part_number: 629105150521; Mistral Part No: 150019050015-R; Package: SMD; Part_type: CONNECTOR\USB; Project: NEXTNAV_ALT-STATION_ATE_BRD; RoHS: RoHS; Temperature: -40°C+85°C; Tolerance: NA; Voltage: NA; Wattage: NA; Weight: 360mg; Datasheet: Y:\MIS_DATABASE\DATASHEETS\CONNECTORS\629105150521.PDF
LD14 = DIODE_LED: DIODE LED BRIGHT GREEN SMD; Chkd/date: MANIRAJA/180820; Crtd /date: ALVY/180820; Custom_Duty: 24%; Customs_HS_Code: 85439000; Distributor_name: DIGIKEY; Distributor_part_number: 732-4986-1-ND; Footprint Path: Y:\MIS_DATABASE\Library\ALTIUM_TOOL\PCB_FOOTPRINTS\Altium_Footprint_Lib.PcbLib; Height: 0.80MM; Library Path: Y:\MIS_DATABASE\Library\ALTIUM_TOOL\SCHEMATICS_PARTS\MS_OPTO_Library.schlib; Mfr_name: WURTH ELECTRONICS; Mistral Part No: 130020080012-R; Package: SMD; Part_type: OPTO\LED; Project: AM64x_EVM_BRD; RoHS: RoHS; Temperature: -40°C+85°C; Tolerance: NA; Voltage: NA; Wattage: NA; Weight: 10mg; Datasheet: Y:\MIS_DATABASE\DATASHEETS\DISCRETES\LEDS\150080VS75000.PDF
LD15 = DIODE_LED: DIODE LED RED SMD; Chkd/date: MANIRAJA/100920; Crtd /date: ALVY/100920; Custom_Duty: 24%; Customs_HS_Code: 85439000; Distributor_name: DIGIKEY; Distributor_part_number: 732-13422-1-ND; Footprint Path: Y:\MIS_DATABASE\Library\ALTIUM_TOOL\PCB_FOOTPRINTS\Altium_Footprint_Lib.PcbLib; Height: 0.35MM; Library Path: Y:\MIS_DATABASE\Library\ALTIUM_TOOL\SCHEMATICS_PARTS\MS_OPTO_Library.schlib; Mfr_name: WURTH ELECTRONICS; Mistral Part No: 130020090020-R; Package: SMD; Part_type: OPTO\LED; Project: AM64X_SKEVM; RoHS: RoHS; Temperature: -40°C+85°C; Tolerance: NA; Voltage: NA; Wattage: NA; Weight: 29.3mg; Datasheet: Y:\MIS_DATABASE\DATASHEETS\DISCRETES\LEDS\150040RS73220.PDF
R228 = RESISTOR: RES 49.9E 1/16W 1% 0402; Chkd/date: MANIRAJA/210519; Crtd /date: MANIRAJA/210519; Custom_Duty: 15%; Customs_HS_Code: 85332119; Distributor_name: DIGIKEY; Distributor_part_number: 541-3967-1-ND; Footprint Path: Y:\MIS_DATABASE\Library\ALTIUM_TOOL\PCB_FOOTPRINTS\Altium_Footprint_Lib.PcbLib; Height: 0.35MM; Library Path: Y:\MIS_DATABASE\Library\ALTIUM_TOOL\SCHEMATICS_PARTS\MS_DISCRETE_Library.schlib; Mfr_name: VISHAY; Mfr_part_number: CRCW040249R9FKEDC; Mistral Part No: 110009030846-R; Package: 0402; Part_type: RESISTORS\FIXED; Project: RFSU_RFTJ_CARD; RoHS: RoHS; Temperature: -55°C+155°C; Tolerance: 1%; Voltage: NA; Wattage: 1/16W; Weight: 0.65mg; Datasheet: Y:\MIS_DATABASE\DATASHEETS\RESISTORS\CRCW_C-SER.PDF
R256 = RESISTOR: RES 0E 1/10W 5% 0603; Chkd/date: MANIRAJA/051217; Crtd /date: BAVISH/180211; Custom_Duty: 15%; Customs_HS_Code: 85332119; Distributor_name: DIGIKEY; Distributor_part_number: 311-0.0GRCT-ND; Footprint Path: Y:\MIS_DATABASE\Library\ALTIUM_TOOL\PCB_FOOTPRINTS\Altium_Footprint_Lib.PcbLib; Height: 0.55MM; Library Path: Y:\MIS_DATABASE\Library\ALTIUM_TOOL\SCHEMATICS_PARTS\MS_DISCRETE_Library.schlib; Manufacturer: YAGEO AMERICA; Mfr_name: PANASONIC-ECG; Mfr_part_number: RC0603JR-070RL; Mistral Part No: 110011020013-R; Package: 0603; Part_type: RESISTORS\FIXED; Project: KENNEL; RoHS: RoHS; Temperature: -55°C+155°C; Tolerance: 5%; Voltage: NA; Wattage: 1/10W; Weight: 2mg; Datasheet: Y:\MIS_DATABASE\DATASHEETS\RESISTORS\RCXXXXL-SER_MAR18.PDF
R261 = RESISTOR: RES 4.87K 1/16W 1% 0402; Chkd/date: MAZHAR/150709; Crtd /date: USMAN/150109; Custom_Duty: 15%; Customs_HS_Code: 85332119; Distributor_name: DIGIKEY; Distributor_part_number: P4.87KLCT-ND; Footprint Path: Y:\MIS_DATABASE\Library\ALTIUM_TOOL\PCB_FOOTPRINTS\Altium_Footprint_Lib.PcbLib; Height: 0.40MM; Library Path: Y:\MIS_DATABASE\Library\ALTIUM_TOOL\SCHEMATICS_PARTS\MS_DISCRETE_Library.schlib; Mfr_name: PANASONIC-ECG; Mfr_part_number: ERJ2RKF4871X; Mistral Part No: 110009030803-R; Package: 0402; Part_type: RESISTORS\FIXED; Project: BSN-II; RoHS: RoHS; Temperature: -55°C+155°C; Tolerance: 1%; Voltage: NA; Wattage: 1/16W; Weight: 0.8mg; Datasheet: Y:\MIS_DATABASE\DATASHEETS\RESISTORS\PAN-ERJSERIES.PDF
R264 R265 R270 = RESISTOR: RES 4.7K 1/20W 5% 0201; Chkd/date: MANIRAJA/200921; Crtd /date: ALVY/200921; Custom_Duty: 15%; Customs_HS_Code: 85332119; Distributor_name: DIGIKEY; Distributor_part_number: 311-4.7KNCT-ND; Footprint Path: Y:\MIS_DATABASE\Library\ALTIUM_TOOL\PCB_FOOTPRINTS\Altium_Footprint_Lib.PcbLib; Height: 0.26MM; Library Path: Y:\MIS_DATABASE\Library\ALTIUM_TOOL\SCHEMATICS_PARTS\MS_DISCRETE_Library.schlib; Mfr_name: YAGEO AMERICA; Mfr_part_number: RC0201JR-074K7L; Mistral Part No: 110021090007-R; Package: 0201; Part_type: RESISTORS\FIXED; Project: TI_AM62x SKEVM_BRD; RoHS: RoHS; Temperature: -55°C+125°C; Tolerance: 5%; Voltage: NA; Wattage: 1/20W; Weight: 0.17mg; Datasheet: Y:\MIS_DATABASE\DATASHEETS\RESISTORS\RCXXXXL-SER_MAR18.PDF
R268 R519 = RESISTOR: RES 30K 1/16W 5% 0402; Chkd/date: MANIRAJA/230817; Crtd /date: MANIRAJA/230817; Custom_Duty: 15%; Customs_HS_Code: 85332119; Distributor_name: DIGIKEY; Distributor_part_number: 541-30KJCT-ND; Footprint Path: Y:\MIS_DATABASE\Library\ALTIUM_TOOL\PCB_FOOTPRINTS\Altium_Footprint_Lib.PcbLib; Height: 0.40MM; Library Path: Y:\MIS_DATABASE\Library\ALTIUM_TOOL\SCHEMATICS_PARTS\MS_DISCRETE_Library.schlib; Mfr_name: VISHAY; Mfr_part_number: CRCW040230K0JNED; Mistral Part No: 110017080023-R; Package: 0402; Part_type: RESISTORS\FIXED; Project: TI_MAXIE_CPB; RoHS: RoHS; Temperature: -55°C+155°C; Tolerance: 5%; Voltage: NA; Wattage: 1/16W; Weight: 0.65mg; Datasheet: Y:\MIS_DATABASE\DATASHEETS\RESISTORS\CRCW0603.PDF
R269 = RESISTOR: RES 20K 1/16W 1% 0402; Chkd/date: MANIRAJA/021120; Crtd /date: MANIRAJA/021120; Custom_Duty: 15%; Customs_HS_Code: 85332119; Distributor_name: DIGIKEY; Distributor_part_number: 541-20.0KLCT-ND; Footprint Path: Y:\MIS_DATABASE\Library\ALTIUM_TOOL\PCB_FOOTPRINTS\Altium_Footprint_Lib.PcbLib; Height: 0.40MM; Library Path: Y:\MIS_DATABASE\Library\ALTIUM_TOOL\SCHEMATICS_PARTS\MS_DISCRETE_Library.schlib; Mfr_name: VISHAY; Mfr_part_number: CRCW040220K0FKED; Mistral Part No: 110009030486-R; Package: 0402; Part_type: RESISTORS\FIXED; Project: VAGG_SBC_BRD; RoHS: RoHS; Temperature: -55°C+155°C; Tolerance: 1%; Voltage: NA; Wattage: 1/16W; Weight: 0.65mg; Datasheet: Y:\MIS_DATABASE\DATASHEETS\RESISTORS\CRCW0603.PDF
R520 = RESISTOR: RES 51K 1/16W 5% 0402; Chkd/date: MANIRAJA/230817; Crtd /date: MANIRAJA/230817; Custom_Duty: 15%; Customs_HS_Code: 85332119; Distributor_name: DIGIKEY; Distributor_part_number: 541-51KJCT-ND; Footprint Path: Y:\MIS_DATABASE\Library\ALTIUM_TOOL\PCB_FOOTPRINTS\Altium_Footprint_Lib.PcbLib; Height: 0.40MM; Library Path: Y:\MIS_DATABASE\Library\ALTIUM_TOOL\SCHEMATICS_PARTS\MS_DISCRETE_Library.schlib; Mfr_name: VISHAY; Mfr_part_number: CRCW040251K0JNED; Mistral Part No: 110009030966-R; Package: 0402; Part_type: RESISTORS\FIXED; Project: TI_MAXIE_CPB; RoHS: RoHS; Temperature: -55°C+155°C; Tolerance: 5%; Voltage: NA; Wattage: 1/16W; Weight: 0.65mg; Datasheet: Y:\MIS_DATABASE\DATASHEETS\RESISTORS\CRCW0603.PDF
R530 = RESISTOR: RES 100E 1/16W 1% 0402; Chkd/date: MANIRAJA/060318; Crtd /date: NAVEED/220714; Custom_Duty: 15%; Customs_HS_Code: 85332119; Distributor_name: DIGIKEY; Distributor_part_number: 311-100LRCT-ND; Footprint Path: Y:\MIS_DATABASE\Library\ALTIUM_TOOL\PCB_FOOTPRINTS\Altium_Footprint_Lib.PcbLib; Height: 0.40MM; Library Path: Y:\MIS_DATABASE\Library\ALTIUM_TOOL\SCHEMATICS_PARTS\MS_DISCRETE_Library.schlib; Mfr_name: YAGEO AMERICA; Mfr_part_number: RC0402FR-07100RL; Mistral Part No: 110014070015-R; Package: 0402; Part_type: RESISTORS\FIXED; Project: DLRU; RoHS: RoHS; Temperature: -55°C+155°C; Tolerance: 1%; Voltage: NA; Wattage: 1/16W; Weight: 0.65mg; Datasheet: Y:\MIS_DATABASE\DATASHEETS\RESISTORS\RCXXXXL-SER_MAR18.PDF
U45 = TM4C1294NCPDTT3R_TQFP128: IC 32-BIT MICROCONTROLLER WITH 1MB FLASH TQFP128; Chkd/date: MANIRAJA/220817; Crtd /date: MANIRAJA/220817; Custom_Duty: 15%; Customs_HS_Code: 85423100; Distributor_name: DIGIKEY; Distributor_part_number: TM4C1294NCPDTT3R-ND; Height: 1.20MM; Mfr_name: TEXAS INSTRUMENTS; Mistral Part No: 141217080002-R; Package: TQF9128; Part_type: ICS\DIGITAL\MICROCONTROLLER; Project: TI_MAXIE_CPB; RoHS: RoHS; Temperature: -40°C+105°C; Tolerance: NA; Voltage: NA; Wattage: NA; Weight: 503.5mg; Datasheet: Y:\MIS_DATABASE\DATASHEETS\ICS\DIGITAL\MICROCONTROLLER\TM4C1294NCPD.PDF
U47 = LM4040B25IDCKR_SC70-5: IC PRECISION MICROPOWER SHUNT VOLTAGE REFERENCE SC70-5; Chkd/date: MANIRAJA/230817; Crtd /date: MANIRAJA/230817; Custom_Duty: 15%; Customs_HS_Code: 85423100; Distributor_name: DIGIKEY; Distributor_part_number: 296-20873-1-ND; Height: 1.10MM; Mfr_name: TEXAS INSTRUMENTS; Mistral Part No: 142017080015-R; Package: SC70-5; Part_type: ICS\POWER\VOLTAGE REGULATOR; Project: TI_MAXIE_CPB; RoHS: RoHS; Temperature: -40°C+85°C; Tolerance: NA; Voltage: NA; Wattage: NA; Weight: 30mg; Datasheet: Y:\MIS_DATABASE\DATASHEETS\ICS\POWER\LM4040B25I.PDF
U79 = TPS79601DRBR_SON8: IC 1A HIGH PSRR RF ADJ LDO LINEAR REGULATOR SON8; Chkd/date: MANIRAJA/030518; Crtd /date: MAZHAR/280809; Custom_Duty: 15%; Customs_HS_Code: 85423100; Distributor_name: DIGIKEY; Distributor_part_number: 296-23107-1-ND; Footprint Path: Y:\MIS_DATABASE\Library\ALTIUM_TOOL\PCB_FOOTPRINTS\Altium_Footprint_Lib.PcbLib; Height: 1.00MM; Library Path: Y:\MIS_DATABASE\Library\ALTIUM_TOOL\SCHEMATICS_PARTS\MS_MISCPOWER_Library.schlib; Mfr_name: TEXAS INSTRUMENTS; Mistral Part No: 142009080012-R; Package: SON8; Part_type: ICS\POWER\VOLTAGE REGULATOR; Project: DIO_TXRX; RoHS: RoHS; Temperature: -40°C+125°C; Tolerance: NA; Voltage: NA; Wattage: NA; Weight: 24mg; Datasheet: Y:\MIS_DATABASE\DATASHEETS\MISC\REGULATORS\TPS796XX.PDF
U89 = TPD4E004_SON6: IC 4-CH ESD PROTECTION ARRAY FOR HIGH SPEED DATA INTERFACE SON6; Chkd/date: MANIRAJA/100320; Crtd /date: MUDDU/010310; Custom_Duty: 15%; Customs_HS_Code: 85423100; Distributor_name: DIGIKEY; Distributor_part_number: 296-23618-1-ND; Footprint Path: Y:\MIS_DATABASE\Library\ALTIUM_TOOL\PCB_FOOTPRINTS\Altium_Footprint_Lib.PcbLib; Height: 0.60MM; Library Path: Y:\MIS_DATABASE\Library\ALTIUM_TOOL\SCHEMATICS_PARTS\MS_MISCINTERFACE_Library.schlib; Mfr_name: TEXAS INSTRUMENTS; Mistral Part No: 141010020012-R; Package: SON6; Part_type: ICS\INTERFACE; Project: BUG_BASE-II; RoHS: RoHS; Temperature: -40°C+85°C; Tolerance: NA; Voltage: NA; Wattage: NA; Weight: 3.2mg; Datasheet: Y:\MIS_DATABASE\DATASHEETS\ICS\INTERFACE\TPD4E004-SER.PDF
Y2 = CRY4_13: CRY 16.000MHz 8pF SMD; Chkd/date: MANIRAJA/151020; Crtd /date: ALVY/151020; Custom_Duty: 24%; Customs_HS_Code: 85439000; Distributor_name: DIGIKEY; Distributor_part_number: 490-18283-1-ND; Footprint Path: Y:\MIS_DATABASE\Library\ALTIUM_TOOL\PCB_FOOTPRINTS\Altium_Footprint_Lib.PcbLib; Height: 0.70MM; Library Path: Y:\MIS_DATABASE\Library\ALTIUM_TOOL\SCHEMATICS_PARTS\MS_DISCRETE_Library.schlib; Mfr_name: MURATA; Mfr_part_number: XRCGB16M000FXN01R0; Mistral Part No: 130020100044-R; Package: SMD; Part_type: CRYSTAL; Project: AM64X_SKEVM; RoHS: RoHS; Temperature: -30°C+85°C; Tolerance: NA; Voltage: NA; Wattage: NA; Weight: 195.4mg; Datasheet: Y:\MIS_DATABASE\DATASHEETS\MISC\CRY_OSC\XRCGB16M000FXN01R0.PDF

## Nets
DGND: C167.2 C169.1 C170.1 C171.1 C172.1 C173.1 C176.2 C178.2 C179.2 C180.2 C181.2 C185.1 C186.2 C189.2 C190.1 C191.2 C192.2 C430.1 C431.2 C439.1 C440.2 C442.1 C443.2 C449.1 C454.2 C455.2 C468.1 C532.1 D8.1 J16.5(GND) LD14.1(CATHODE) LD15.1(CATHODE) R202.2 R203.2 R204.2 R205.2 R206.2 R207.2 R208.2 R209.2 R210.2 R211.2 R212.2 R213.2 R214.2 R215.2 R216.2 R217.2 R252.1 R255.1 R256.1 R258.1 R259.1 R260.1 R261.2 R269.2 R519.2 R521.2 R527.1 R546.2 U43.3(GND) U45.10(GNDA) U45.17(GND) U45.48(GND) U45.55(GND) U45.58(GND) U45.64(~{WAKE}) U45.66(XOSC0) U45.80(GND) U45.114(GND) U47.1(ANODE) U73.11(GND1) U73.12(GND2) U73.13(GND3) U73.25(EP) U74.25(GND) U74.33(EP) U75.11(GND1) U75.12(GND2) U75.13(GND3) U75.25(EP) U79.6(GND) U79.9(PAD) U89.3(GND) Y2.2 Y2.4 ; also on sheet 1 3 12 13 14 15 16 17 18 19 20 21 22 23 24 25 26 27 28 31 32 33 34 35 36 37 38 39 40 41 42 43 44 45
VCC3V3_TA: C167.1 C430.2 C439.2 C442.2 R236.2 R237.2 R238.2 R239.2 R240.2 R241.2 R242.2 R243.2 R244.2 R245.2 R246.2 R247.2 R248.2 R249.2 R250.2 R251.2 R514.2 R517.2 R522.2 U43.5(VCC) U73.1(VCCA) U74.27(VCCP) U74.31(VCC) U75.1(VCCA) ; also on sheet 3 28
VCC3V3_XDS: C173.2 C176.1 C181.1 C189.1 C191.1 C192.1 C441.1 C443.1 C454.1 C468.2 R228.2 R264.1 R265.1 R270.1 R520.1 R539.2 R552.2 R556.2 R560.2 R563.2 TP77.1(TP) U45.7(VDD) U45.8(VDDA) U45.16(VDD) U45.26(VDD) U45.28(VDD) U45.39(VDD) U45.47(VDD) U45.51(VDD) U45.52(VDD) U45.69(VDD) U45.79(VDD) U45.90(VDD) U45.101(VDD) U45.113(VDD) U45.122(VDD) U79.3(OUT1) U79.4(OUT2) ; also on sheet 3 31
VCC_3V3_SYS: C431.1 C440.1 U73.23(VCCB1) U73.24(VCCB2) U75.23(VCCB1) U75.24(VCCB2) ; also on sheet 3 12 14 15 16 20 21 22 24 25 26 27 28 31 32 33 34 35 36 37 38 39 40 41 42 43 44 45
VDDC_1V2: C178.1 C179.1 C449.2 U45.87(VDDC) U45.115(VDDC)
BOOTMODE0: U75.14(B8) ; also on sheet 34
BOOTMODE1: U75.15(B7) ; also on sheet 34
BOOTMODE2: U75.16(B6) ; also on sheet 34
BOOTMODE3: U75.17(B5) ; also on sheet 34
BOOTMODE4: U75.18(B4) ; also on sheet 34
BOOTMODE5: U75.19(B3) ; also on sheet 34
BOOTMODE6: U75.20(B2) ; also on sheet 34
BOOTMODE7: U75.21(B1) ; also on sheet 34
BOOTMODE8: U73.14(B8) ; also on sheet 34
BOOTMODE9: U73.15(B7) ; also on sheet 34
BOOTMODE10: U73.16(B6) ; also on sheet 34
BOOTMODE11: U73.17(B5) ; also on sheet 34
BOOTMODE12: U73.18(B4) ; also on sheet 34
BOOTMODE13: U73.19(B3) ; also on sheet 34
BOOTMODE14: U73.20(B2) ; also on sheet 34
BOOTMODE15: U73.21(B1) ; also on sheet 34
BOOTMODE_I2C_SCL: TP83.1(TP) U74.29(SCL) ; also on sheet 3 28
BOOTMODE_I2C_SDA: TP84.1(TP) U74.30(SDA) ; also on sheet 3 28
BOOTMODE_XDS_I2C_SCL: U45.49(PG0) ; also on sheet 3
BOOTMODE_XDS_I2C_SDA: U45.50(PG1) ; also on sheet 3
BOOTMODEON: R252.2 U43.4(Y) U73.22(~{OE}) U75.22(~{OE})
DIR: R514.1 U73.2(DIR) U75.2(DIR)
IO_EXP_ADDR: R521.1 U74.26(ADDR)
OSC0: C172.2 U45.88(OSC0) Y2.3
OSC1: C171.2 U45.89(OSC1) Y2.1
PORz_OUT: R221.2 ; also on sheet 22 25 26 44
RESETSTATz: R222.2 ; also on sheet 15 21 22 23 25 26 34 35 39 41 42 43 44
SoC_I2C1_XDS_SCL: U45.82(PL1) ; also on sheet 3
SoC_I2C1_XDS_SDA: U45.81(PL0) ; also on sheet 3
SYS_BOOTMODE0: R202.1 SW1.1 U74.1(P00) U75.10(A8)
SYS_BOOTMODE1: R203.1 SW1.2 U74.2(P01) U75.9(A7)
SYS_BOOTMODE2: R204.1 SW1.3 U74.3(P02) U75.8(A6)
SYS_BOOTMODE3: R205.1 SW1.4 U74.4(P03) U75.7(A5)
SYS_BOOTMODE4: R206.1 SW1.5 U74.5(P04) U75.6(A4)
SYS_BOOTMODE5: R207.1 SW1.6 U74.6(P05) U75.5(A3)
SYS_BOOTMODE6: R208.1 SW1.7 U74.7(P06) U75.4(A2)
SYS_BOOTMODE7: R209.1 SW1.8 U74.8(P07) U75.3(A1)
SYS_BOOTMODE8: R210.1 SW2.1 U73.10(A8) U74.9(P10)
SYS_BOOTMODE9: R211.1 SW2.2 U73.9(A7) U74.10(P11)
SYS_BOOTMODE10: R212.1 SW2.3 U73.8(A6) U74.11(P12)
SYS_BOOTMODE11: R213.1 SW2.4 U73.7(A5) U74.12(P13)
SYS_BOOTMODE12: R214.1 SW2.5 U73.6(A4) U74.13(P14)
SYS_BOOTMODE13: R215.1 SW2.6 U73.5(A3) U74.14(P15)
SYS_BOOTMODE14: R216.1 SW2.7 U73.4(A2) U74.15(P16)
SYS_BOOTMODE15: R217.1 SW2.8 U73.3(A1) U74.16(P17)
SYSBOOT_BUF_ENz: R221.1 R222.1 U43.1(A)
TCA6424_EXP_INT: R522.1 U74.32(~{INT})
TEST_GPIO1_XDS: U45.74(PM4) ; also on sheet 3
TEST_GPIO2_XDS: U45.73(PM5) ; also on sheet 3
TEST_GPIO3: J14.1 R517.1 U43.2(B) ; also on sheet 3 28
TEST_GPIO3_XDS: U45.72(PM6) ; also on sheet 3
TEST_GPIO4: U74.28(~{RESET}) ; also on sheet 3 28
TEST_GPIO4_XDS: U45.71(PM7) ; also on sheet 3
TEST_PORZn_XDS: U45.77(PM1) ; also on sheet 3
TEST_POWERDOWN_XDS: U45.78(PM0) ; also on sheet 3
TEST_WARMRESETn_XDS: U45.76(PM2) ; also on sheet 3
TM4C129_TCK: TP82.1(TP) U45.100(PC0/TCK/SWCLK)
TM4C129_TDI: TP80.1(TP) U45.98(PC2/TDI)
TM4C129_TDO: TP79.1(TP) U45.97(PC3/TDO/SWO)
TM4C129_TMS: TP81.1(TP) U45.99(PC1/TMS/SWDIO)
XDS110_EMU0: R265.2 U45.42(PF0) ; also on sheet 31
XDS110_EMU1: R264.2 U45.43(PF1) ; also on sheet 31
XDS110_TCK: U45.35(PA2/SSI0CLK) ; also on sheet 31
XDS110_TDI: U45.38(PA5/SSI0XDAT1) ; also on sheet 31
XDS110_TDO: U45.37(PA4/SSI0XDAT0) ; also on sheet 31
XDS110_TMS: U45.36(PA3/SSI0FSS) ; also on sheet 31
XDS110_TRST#: U45.40(PA6) ; also on sheet 31
XDS_RSTn: R539.1 R546.1 TP75.1(TP) U45.70(~{RST})
XDS_SHIELD: C185.2 J16.6(SH1) J16.7(SH2) J16.8(SH3) J16.9(SH4) R256.2
XDS_USB_DM: J16.2(D-) U45.93(PL7/USB0DM) U89.5(IO4)
XDS_USB_DP: J16.3(D+) U45.94(PL6/USB0DP) U89.4(IO3)
XDS_USB_ID: J16.4(ID) R235.2 U89.2(IO2)
XDS_USB_VBUS: C180.1 C455.1 C532.2 D8.2 J16.1(VBUS) R268.1 R530.1 R540.1 TP86.1(TP) U79.1(IN1) U79.2(IN2) U89.6(VCC)
XDS_VREF: C186.1 C190.2 R270.2 U45.9(VREFA+) U47.3(CATHODE)
N16997746: R261.1 U45.59(RBAIS)
N17078351: R239.1 SW1.13
N17078353: R238.1 SW1.14
N17078355: R237.1 SW1.15
N17078357: R236.1 SW1.16
N17078758: R249.1 SW2.11
N17078760: R248.1 SW2.12
N17078762: R247.1 SW2.13
N17078764: R246.1 SW2.14
N17078766: R251.1 SW2.9
N17078768: R250.1 SW2.10
N17078770: R245.1 SW2.15
N17078778: R244.1 SW2.16
N17078974: J14.2 R527.2
N17084256: R243.1 SW1.9
N17084257: R242.1 SW1.10
N17084258: R241.1 SW1.11
N17084259: R240.1 SW1.12
N17479799: R540.2 U79.8(EN)
N17479805: C441.2 R519.1 R520.2 U79.5(NR/FB)
N17479881: C169.2 R228.1 U45.68(VBAT)
N17481587: LD14.2(ANODE) R267.1
N17481598: C170.2 R530.2 U45.96(PB1/USB0VBUS)
N17481613: R235.1 U45.95(PB0/USB0ID)
N17481619: R268.2 R269.1 U45.1(PD0/AIN15)
N17481621: R260.2 R563.1 U45.60(PK7)
N17481627: R271.2 U45.3(PD2/AIN13)
N17481631: LD15.2(ANODE) R271.1
N17481633: R255.2 R552.1 U45.63(PK4)
N17481635: R259.2 R560.1 U45.61(PK6)
N17481637: R267.2 U45.4(PD3/AIN12)
N17481641: R258.2 R556.1 U45.62(PK5)
N18374561: TP76.1(TP) U45.75(PM3)

Not connected (* = marked no-connect by the designer): U45 2(PD1/AIN14)* 5(PQ0)* 6(PQ1)* 11(PQ2)* 12(PE3/AIN0)* 13(PE2/AIN1)* 14(PE1/AIN2)* 15(PE0/AIN3)* 18(PK0/AIN16)* 19(PK1/AIN17)* 20(PK2/AIN18)* 21(PK3/AIN19)* 22(PC7/C0-)* 23(PC6/C0+)* 24(PC5/C1+)* 25(PC4/C1-)* 27(PQ3)* 29(PH0)* 30(PH1)* 31(PH2)* 32(PH3)* 33(PA0/U0RX)* 34(PA1/U0TX)* 41(PA7)* 44(PF2)* 45(PF3)* 46(PF4)* 53(EN0RXIN)* 54(EN0RXIP)* 56(EN0RX0N)* 57(EN0RX0P)* 65(~{HIB})* 67(XOSC1)* 83(PL2)* 84(PL3)* 85(PL4)* 86(PL5)* 91(PB2/I2C0SCL)* 92(PB3/I2C0SDA)* 102(PQ4)* 103(PP2)* 104(PP3)* 105(PP4)* 106(PP5)* 107(PN0)* 108(PN1)* 109(PN2)* 110(PN3)* 111(PN4)* 112(PN5)* 116(PJ0)* 117(PJ1)* 118(PP0/C2+)* 119(PP1/C2-)* 120(PB5/AIN11)* 121(PB4/AIN10)* 123(PE4/AIN9)* 124(PE5/AIN8)* 125(PD4/AIN7)* 126(PD5/AIN6)* 127(PD6/AIN5)* 128(PD7/AIN4)*; U47 2(NC1)* 4(NC2)* 5(NC3)*; U74 17(P20)* 18(P21)* 19(P22)* 20(P23)* 21(P24)* 22(P25)* 23(P26)* 24(P27)*; U79 7(NC)*; U89 1(IO1)*

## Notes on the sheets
sheet 29
- BOOT MODE BUFFERS
- BOOTMODE IO EXPANDER
- D-Note:
  Boot mode buffers are optional for custom board.
- D-Note:
  Add an additional decap.
  Verify and terminate unused IOs.
- DIR = H: A -> B
  DIR = L: B -> A
  OE = H: output = Hi-Z
- DIR = H: A -> B
  DIR = L: B -> A
  OE = H: output = Hi-Z
- I2C ADDRESS: 0x22
- BOOTMODE CONFIGURATION RESISTORS
          AND BOOTMODE SWITCHES
- D-Note:
  Connect bootmode configuration pullups to VCC_3V3_SYS
  when test automation is not used on the custom board
- D-Note:
  VCC3V3_TA supply is used to support test automation.
  Connect bootmode configuration pullup resistors to
  SoC_DVDD3V3 on the custom board design when test
  automation and buffers are not used.
- D-Note:
  The recommendation is to not
  leave any of the bootmode
  pins unconnected (open)
  including the reserved pins.
- D-Note:
  1. Dip switches are used on the SK for ease of configuration.
  DIP switches are optional on the custom board. A pull-up or pull-down
  resistor can be used to set the bootmode configuration. Provide provisions
  for pull-up and pull-down resistors for the bootmode pins that have
  configuration capability.
  2. When DIP switches are used on the custom board, provision for an external
  ESD protection may be required if the DIP switches are expected to be
  configured in an uncontrolled ESD environment.
  3. When DIP switches are used, reduce the resistor values used for the divider
  to 47k and 2K (1K) ohms to optimize the current draw in case the IOs are used
  for alternate functions (output).
- SWITCH ON  =  LOGIC 1
  SWITCH OFF =  LOGIC 0
- BOOT MODES SUPPORTED
- Silk: BMODE 0-7
- Silk: BMODE 8-15
- 1. OSPI
- 2. MMC1 - SD CARD
- 3. UART
- 4. eMMC
- 5. USB0 DFU
- 6. BACKUP BOOT OPTION
- FAQs FOR REFERENCE TO IMPLEMENT BOOTMODE CONFIGURATION (WITH BUFFER OR WITHOUT BUFFER):
- https://e2e.ti.com/support/processors-group/processors/f/processors-forum/1391522/faq-am625-am623-am644x-am243x-am62a-am62p-am62d-q1-am62l---bootmode-implementation-without-buffers
- https://e2e.ti.com/support/processors-group/processors/f/processors-forum/1414148/faq-am625-am623-am644x-am243x-am62a-am62p-am62d-q1-am62l---bootmode-implementation-with-buffers
sheet 30
- XDS110 DEBUGGER
- D-Note:
  Please follow SK-AM62P-LP EVM implementations for the latest updates on XDS110.
- Silk: JTAG
- 90E
- GREEN
- RED
- V
- Sets the unique ID of the Debugger
